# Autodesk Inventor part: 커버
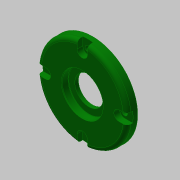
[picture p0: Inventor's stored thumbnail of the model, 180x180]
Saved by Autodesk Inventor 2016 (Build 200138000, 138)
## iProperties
Created: 2020-05
Part Number: 커버
Material: 알루미늄 6061
Document SubType Name: Modeling
Designer: mduedu
Density: 1 g/cm^3
Appearance: 진녹색
Author: mduedu
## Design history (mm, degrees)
sketch "스케치1"
  geometry: L1 (0, 0)-(8, 0); L2 (8, 0)-(8, 35); L3 (8, 35)-(0, 35); L4 (0, 35)-(0, 0); L5 (8, 0)-(12, 0); L6 (12, 0)-(12, 23.5); L7 (12, 23.5)-(8, 23.5); L8 (8, 23.5)-(8, 0)
  constraints: 16 end point, 4 parallel, 2 horizontal, 2 perpendicular
  dimensions: "d0" = 70 diameter of L3 L1; "d2" = 47 diameter of L7 L5; "d3" = 4 distance of L6.end L7.end; "d4" = 12 distance between parallel lines of L4 L6
revolve "회전1" sketch "스케치1" stored, may be unused: angle "d5" = 90 deg
hole "구멍1" diameter "d8" = 22; stored, may be unused: countersink angle "d12" = 90 deg, drill point angle "d14" = 118 deg; dims "d6" = 10, "d7" = 10, "d9" = 6, "d10" = 32, "d11" = 5.2, "d13" = 8
hole "구멍2" diameter "d17" = 40; stored, may be unused: countersink angle "d21" = 90 deg, drill point angle "d23" = 0 deg; dims "d15" = 10, "d16" = 10, "d18" = 6, "d19" = 32, "d20" = 5.2, "d22" = 4
fillet "모깎기1" dims "d24" = 3
fillet "모깎기2" dims "d25" = 3
fillet "모깎기3" dims "d26" = 0.3
chamfer "모따기1" distance "d27" = 0.5; stored, may be unused: second distance "d28" = 2, angle "d29" = 30 deg
chamfer "모따기2" distance "d30" = 1; stored, may be unused: second distance "d31" = 2, angle "d32" = 30 deg
sketch "스케치2" dims "d33" = 57
  geometry: L1 (-4, 28.5)-(4, 28.5); L2 (4, 28.5)-(4, 38.5); L3 (4, 38.5)-(-4, 38.5); L4 (-4, 38.5)-(-4, 28.5); 4 further points
  constraints: 8 end point, 2 horizontal alignment, 2 midpoint, 2 parallel, 2 vertical alignment, 1 coincident, 1 horizontal, 1 perpendicular, 6 other
  dimensions: "d34" = 8 distance between parallel lines of L2 L4; "d35" = 10 distance of point (0, 28.5) point (0, 38.5)
extrude "돌출1" cut sketch "스케치2" distance "d36" = 4.4; taper "d37" = 0 deg
sketch "스케치3"
  geometry: A1 r 4 centre (0, 28.5) between (-4, 28.5) and (4, 28.5) reference; 2 further points
  constraints: 1 coincident
hole "구멍3" sketch "스케치3" at (0, 28.5) diameter "d38" = 4.5; stored, may be unused: countersink angle "d42" = 90 deg, drill point angle "d44" = 0 deg; dims "d39" = 6, "d40" = 32, "d41" = 5.2, "d43" = 4
node "솔리드1"
pattern_circular "원형 패턴1" dims angle "d46" = 360 deg
